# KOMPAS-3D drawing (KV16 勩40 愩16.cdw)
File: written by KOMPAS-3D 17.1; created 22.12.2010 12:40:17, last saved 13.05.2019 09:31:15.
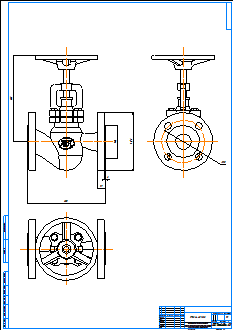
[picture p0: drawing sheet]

Title block, sheet 1: name: KV16 Ду40 Ру16; material: Внимание! Данный продукт является объектом авторского права ООО «Торговый Дом АДЛ». / Запрещается изменение, копирование, распространение / (в том числе путем копирования на другие сайты и ресурсы в Интернете) / или любое иное использование информации и объектов без предварительного / согласия правообладателя (ООО «Торговый Дом АДЛ»).; scale: 1:1; sheets: 1; organisation: ООО "Торговый дом АДЛ"; sheet format: A1; stored path: \\adlc.lan\data\АДЛ_ПКД\3D-модели\ADL production\Вентили ГРАНВЕНТ\KV16\KOMPAS 2D\KV16 Ду40 Ру16.cdw

Views: Спереди 1, Проекционный вид 2, Вид 5
Dimensions and other numbers on the sheet: 84; 150; 2; 19; 200; 110; 220; 1:1; 1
